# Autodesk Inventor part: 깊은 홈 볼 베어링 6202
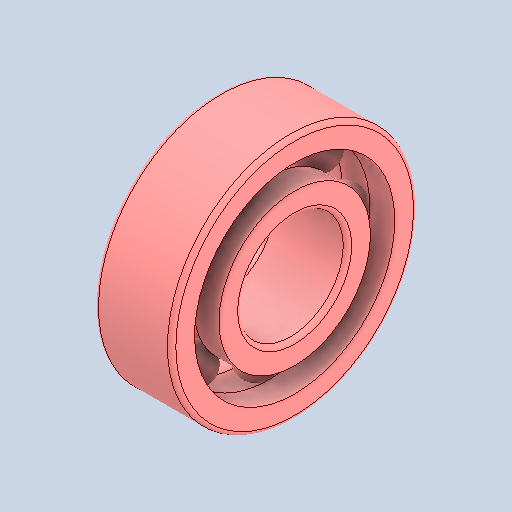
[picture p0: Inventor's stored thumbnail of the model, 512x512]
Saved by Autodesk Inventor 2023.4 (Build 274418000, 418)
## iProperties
Created: 2024-10
Part Number: 깊은 홈 볼 베어링 6202
Material: 강철, 연강
Description: 깊은 그루브 볼 베어링
Document SubType Name: Modeling
Designer: EDU
Density: 7.85 g/cm^3
Appearance: 기본값
Author: jhkim
Sending System: Autodesk Inventor 2025
Preprocessor: ST-DEVELOPER v20
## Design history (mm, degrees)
node "깊음 홈 볼 베어링 62021"
node "솔리드1"
node "솔리드2"
node "솔리드3"
node "솔리드4"
node "솔리드5"
node "솔리드6"
node "솔리드7"
node "솔리드8"
node "솔리드9"
node "솔리드10"
body "Solid1"
node "Solid1:1"
node "Solid1:2"
node "Solid1:3"
node "Solid1:4"
node "Solid1:5"
node "Solid1:6"
node "Solid1:7"
node "Solid1:8"
node "Solid1:9"
